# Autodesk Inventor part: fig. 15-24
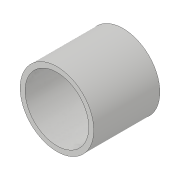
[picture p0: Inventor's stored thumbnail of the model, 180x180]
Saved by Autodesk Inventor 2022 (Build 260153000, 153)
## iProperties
Created: 2018-03
Part Number: fig. 15-24
Material: Generic
Document SubType Name: Modeling
Designer: CADCIM 00
Density: 1 g/cm^3
Appearance: Default
Author: CADCIM 00
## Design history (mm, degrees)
sketch "Sketch1"
  geometry: C1 r 14.209 at (0.32, 0); C2 r 12.286 at (0.32, 0); 1 further point
  constraints: 2 centre point, 1 coincident
  dimensions: "d0" = 25.5 dimension on point (0, 0) C1.centre C1 C2.centre C2
extrude "Extrusion1" new body sketch "Sketch1" distance "d0" = 25.5; taper "d1" = 0 deg
body "Solid1"
